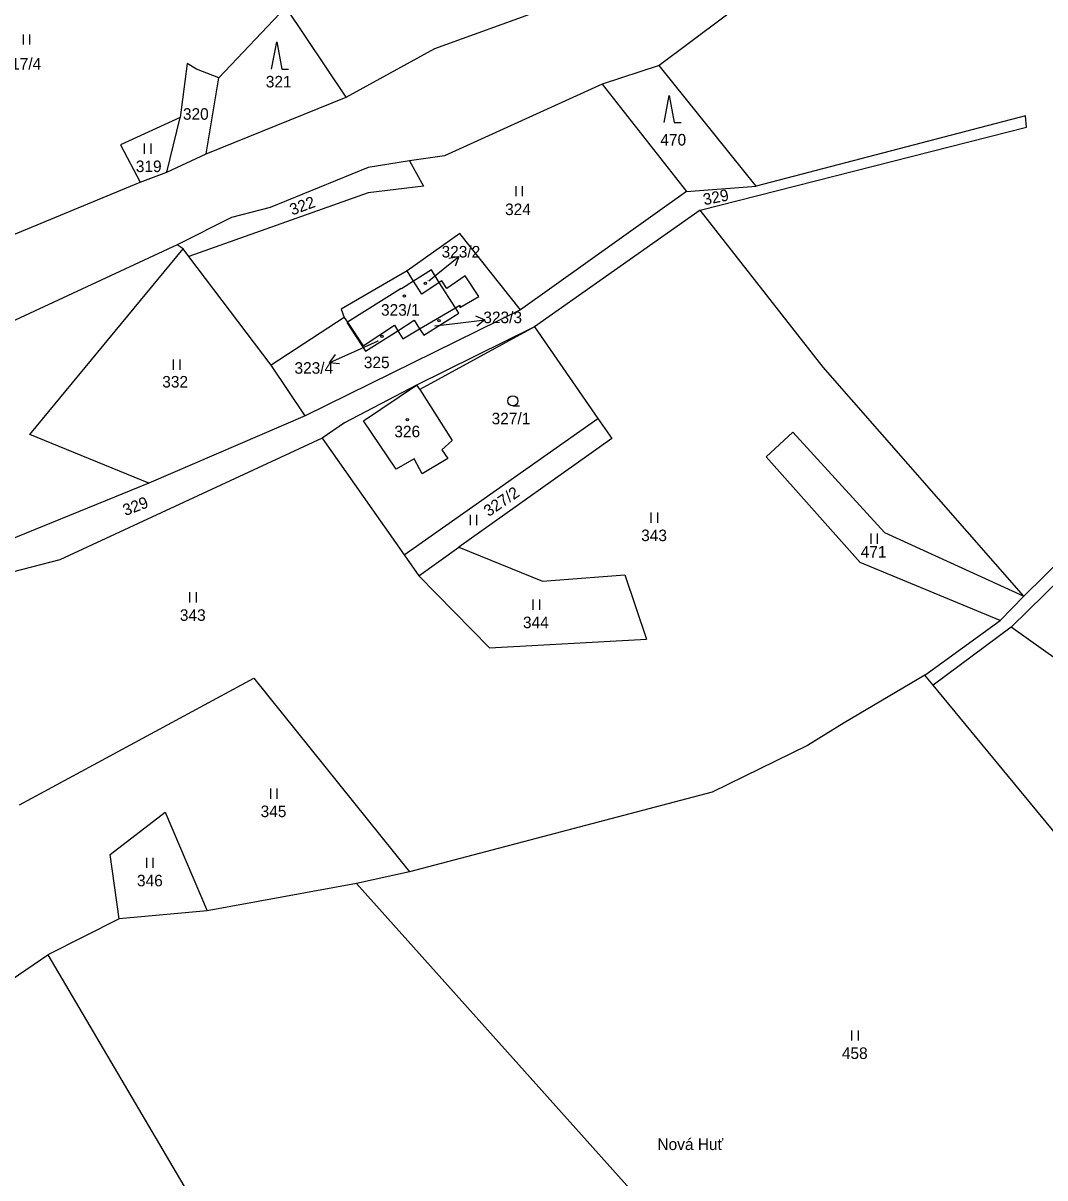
# Model space of a CAD drawing. Extents: x -670359 to -668019, y -978807 to -976674.
# Drawn here: x -669029.4 to -668879.1, y -977159.1 to -976989.2 of the extents above; entities that cross this region are included whole.
import ezdxf

# ---------------------------------------------------------------- set-up
doc = ezdxf.new("R2010")
doc.units = 0
for name, color, linetype in [('Hranice parcel', 7, 'Continuous'), ('Parcelní čísla', 7, 'Continuous'), ('Pop  PČ popisy', 7, 'Continuous'), ('Vnitřní kresba', 7, 'Continuous'), ('Značky budov', 7, 'Continuous'), ('Značky kultur', 7, 'Continuous')]:
    doc.layers.add(name, color=color, linetype=linetype)

msp = doc.modelspace()

# ---------------------------------------------------------------- linework, layer by layer
at = {"layer": 'Hranice parcel'}
for points in [[(-668916.6, -976981.01), (-668935.83, -976995.43)], [(-668990.71, -976986.86), (-669000.59, -976997.23)], [(-668981.86, -977000.08), (-668990.71, -976986.86)], [(-668968.82, -976992.93), (-668953.09, -976987.25)], [(-668981.86, -977000.08), (-668968.82, -976992.93)], [(-669005.23, -976995.14), (-669006.29, -977003.05)], [(-669003.87, -976995.94), (-669005.23, -976995.14)], [(-669001.47, -976996.91), (-669003.87, -976995.94)], [(-668935.83, -976995.43), (-668944.22, -976998.16)], [(-668921.54, -977013.15), (-668935.83, -976995.43)], [(-669002.47, -977008.43), (-669000.59, -976997.23)], [(-669000.59, -976997.23), (-669001.47, -976996.91)], [(-668944.22, -976998.16), (-668967.4, -977008.72)], [(-668944.22, -976998.16), (-668931.79, -977013.98)], [(-669002.47, -977008.43), (-668981.86, -977000.08)], [(-668881.92, -977002.82), (-668921.54, -977013.15)], [(-668881.8, -977004.5), (-668881.92, -977002.82)], [(-669006.29, -977003.05), (-669015.04, -977007.11)], [(-669008.24, -977011.13), (-669006.29, -977003.05)], [(-668929.8, -977016.71), (-668881.8, -977004.5)], [(-669015.04, -977007.11), (-669012.17, -977012.56)], [(-669008.24, -977011.13), (-669002.47, -977008.43)], [(-668972.53, -977009.47), (-668978.62, -977010.45)], [(-668967.4, -977008.72), (-668972.53, -977009.47)], [(-668972.53, -977009.47), (-668970.46, -977013.15)], [(-669012.17, -977012.56), (-669008.24, -977011.13)], [(-668978.62, -977010.45), (-668993.05, -977016.29)], [(-669052.45, -977029.26), (-669012.17, -977012.56)], [(-668978.63, -977014.17), (-669005, -977023.5)], [(-668970.46, -977013.15), (-668978.63, -977014.17)], [(-668931.79, -977013.98), (-668956.19, -977031.36)], [(-668931.79, -977013.98), (-668921.54, -977013.15)], [(-668993.05, -977016.29), (-668998.74, -977017.8)], [(-668998.74, -977017.8), (-669006.72, -977021.8)], [(-668929.8, -977016.71), (-668954.16, -977033.88)], [(-668911.7, -977039.8), (-668929.8, -977016.71)], [(-668965.12, -977020.13), (-668972.9, -977025.63)], [(-668956.19, -977031.36), (-668965.12, -977020.13)], [(-669006.72, -977021.8), (-669055.8, -977044.62)], [(-669028.39, -977049.72), (-669005.85, -977022.4)], [(-669005.85, -977022.4), (-669006.72, -977021.8)], [(-669005, -977023.5), (-669005.85, -977022.4)], [(-668992.89, -977039.49), (-669005, -977023.5)], [(-668972.9, -977025.63), (-668982.61, -977031.28)], [(-668971.95, -977027.15), (-668972.9, -977025.63)], [(-668968.16, -977027.33), (-668969.32, -977025.5), (-668971.95, -977027.15)], [(-668964.34, -977026.37), (-668967.07, -977028.21)], [(-668962.35, -977029.42), (-668964.34, -977026.37)], [(-668970.75, -977029.08), (-668971.95, -977027.15)], [(-668968.16, -977027.33), (-668970.75, -977029.08)], [(-668967.78, -977027.08), (-668968.16, -977027.33)], [(-668967.07, -977028.21), (-668967.78, -977027.08)], [(-668965.15, -977031.01), (-668962.35, -977029.42)], [(-668956.19, -977031.36), (-668987.87, -977046.95)], [(-668982.61, -977031.28), (-668982.13, -977032.48)], [(-668971.05, -977034.18), (-668970.45, -977035.12), (-668965.29, -977031.87), (-668965.79, -977031.07)], [(-668971.05, -977034.18), (-668965.79, -977031.07)], [(-668965.79, -977031.07), (-668965.15, -977030.69)], [(-668965.15, -977030.69), (-668965.15, -977031.01)], [(-668982.13, -977032.48), (-668992.89, -977039.49)], [(-668982.13, -977032.48), (-668981.66, -977033.19)], [(-668981.66, -977033.19), (-668981.74, -977033.25)], [(-668981.74, -977033.25), (-668979.02, -977037.47), (-668974.25, -977034.44)], [(-668981.66, -977033.19), (-668979.35, -977036.65)], [(-668979.35, -977036.65), (-668974.77, -977033.62)], [(-668974.77, -977033.62), (-668974.25, -977034.44)], [(-668974.25, -977034.44), (-668973.5, -977035.63)], [(-668973.5, -977035.63), (-668971.05, -977034.18)], [(-668954.16, -977033.88), (-668971.52, -977042.43)], [(-668954.16, -977033.88), (-668944.83, -977047.37)], [(-668987.87, -977046.95), (-668992.89, -977039.49)], [(-668882.19, -977073.48), (-668911.7, -977039.8)], [(-668849.2, -977041.1), (-668882.19, -977073.48)], [(-668971.52, -977042.43), (-668982.11, -977048.01)], [(-668979.3, -977047.69), (-668971.52, -977042.43)], [(-668971.52, -977042.43), (-668971.04, -977043.08)], [(-668971.04, -977043.08), (-668966.26, -977050.61)], [(-668847.36, -977042.09), (-668884.04, -977078.04)], [(-668987.87, -977046.95), (-669010.88, -977056.89)], [(-668982.11, -977048.01), (-668985.4, -977050.24)], [(-668974.52, -977054.83), (-668979.3, -977047.69)], [(-668973.34, -977067.43), (-668944.83, -977047.37)], [(-668944.83, -977047.37), (-668942.8, -977050.3)], [(-669010.88, -977056.89), (-669028.39, -977049.72)], [(-668985.4, -977050.24), (-669023.97, -977068.13)], [(-668985.4, -977050.24), (-668973.34, -977067.43)], [(-668942.8, -977050.3), (-668965.27, -977066.29)], [(-668920.07, -977052.98), (-668916.14, -977049.39)], [(-668916.14, -977049.39), (-668902.65, -977064.15)], [(-668966.26, -977050.61), (-668967.79, -977051.97)], [(-668967.79, -977051.97), (-668966.91, -977053.25)], [(-668971.87, -977053.31), (-668974.52, -977054.83)], [(-668970.68, -977055.48), (-668971.87, -977053.31)], [(-668966.91, -977053.25), (-668970.68, -977055.48)], [(-668906.27, -977068.54), (-668920.07, -977052.98)], [(-669010.88, -977056.89), (-669036.7, -977067.38)], [(-668902.65, -977064.15), (-668882.19, -977073.48)], [(-668973.34, -977067.43), (-668971.19, -977070.5)], [(-668971.19, -977070.5), (-668965.27, -977066.29)], [(-668965.27, -977066.29), (-668952.96, -977071.29)], [(-669023.97, -977068.13), (-669038.07, -977071.77)], [(-668885.64, -977077.08), (-668906.27, -977068.54)], [(-668971.19, -977070.5), (-668960.76, -977081.11)], [(-668952.96, -977071.29), (-668940.87, -977070.36)], [(-668940.87, -977070.36), (-668937.7, -977079.81)], [(-668885.64, -977077.08), (-668882.19, -977073.48)], [(-668896.72, -977085.13), (-668885.64, -977077.08)], [(-668884.04, -977078.04), (-668895.52, -977086.57)], [(-668843.95, -977106.55), (-668884.04, -977078.04)], [(-668960.76, -977081.11), (-668937.7, -977079.81)], [(-669029.93, -977104.2), (-668995.44, -977085.57)], [(-668995.44, -977085.57), (-668972.56, -977114.04)], [(-668896.72, -977085.13), (-668908.59, -977092.13)], [(-668895.52, -977086.57), (-668896.72, -977085.13)], [(-668863.63, -977125.22), (-668895.52, -977086.57)], [(-668908.59, -977092.13), (-668913.97, -977095.48)], [(-668913.97, -977095.48), (-668928, -977102.32)], [(-668928, -977102.32), (-668972.56, -977114.04)], [(-669016.59, -977111.52), (-669008.48, -977105.3)], [(-669008.48, -977105.3), (-669002.28, -977119.8)], [(-669015.26, -977120.96), (-669016.59, -977111.52)], [(-668972.56, -977114.04), (-668980.33, -977115.78)], [(-668980.33, -977115.78), (-669002.28, -977119.8)], [(-668932.58, -977169.12), (-668980.33, -977115.78)], [(-669002.28, -977119.8), (-669015.26, -977120.96)], [(-669015.26, -977120.96), (-669025.76, -977126.29)], [(-669031.15, -977129.95), (-669025.76, -977126.29)], [(-669025.76, -977126.29), (-668965.38, -977228.83)]]:
    msp.add_lwpolyline(points, dxfattribs=at)
at = {"layer": 'Parcelní čísla'}
for p, q in [((-668966.74, -977023.75), (-668965.26, -977023.52)), ((-668969.71, -977027.08), (-668968.38, -977026.02)), ((-668968.81, -977033.7), (-668965.42, -977033.31)), ((-668962.82, -977032.26), (-668961.45, -977032.85)), ((-668977.22, -977035.98), (-668980.68, -977037.53)), ((-668982.84, -977039.32), (-668984.33, -977039.16))]:
    msp.add_line(p, q, dxfattribs=at)
for points in [[(-668968.38, -977026.02), (-668965.26, -977023.52), (-668965.8, -977024.92)], [(-668965.42, -977033.31), (-668961.45, -977032.85), (-668962.65, -977033.75)], [(-668980.68, -977037.53), (-668984.33, -977039.16), (-668983.45, -977037.95)]]:
    msp.add_lwpolyline(points, dxfattribs=at)
at = {"layer": 'Vnitřní kresba'}
for p, q in [((-668973.77, -977028.21), (-668981.66, -977033.19)), ((-668973.72, -977028.29), (-668973.77, -977028.21)), ((-668971.95, -977027.15), (-668973.72, -977028.29)), ((-668965.79, -977031.07), (-668968.16, -977027.33)), ((-668974.25, -977034.44), (-668971.86, -977032.91)), ((-668971.86, -977032.91), (-668971.05, -977034.18))]:
    msp.add_line(p, q, dxfattribs=at)
msp.add_lwpolyline([(-668954.16, -977033.88), (-668971.04, -977043.08)], dxfattribs=at)
at = {"layer": 'Značky budov'}
for centre in [(-668973.3, -977029.35), (-668972.88, -977047.52)]:
    msp.add_circle(centre, 0.175, dxfattribs=at)
at = {"layer": 'Značky kultur'}
for p, q in [((-669029.37, -976990.84), (-669029.37, -976992.34)), ((-669028.37, -976992.34), (-669028.37, -976990.84)), ((-669011.55, -977006.9), (-669011.55, -977008.4)), ((-669010.55, -977008.4), (-669010.55, -977006.9)), ((-668956.92, -977013.15), (-668956.92, -977014.65)), ((-668955.92, -977014.65), (-668955.92, -977013.15)), ((-669007.3, -977038.69), (-669007.3, -977040.19)), ((-669006.3, -977040.19), (-669006.3, -977038.69)), ((-668957.35, -977045.51), (-668956.35, -977045.51)), ((-668963.64, -977061.53), (-668963.64, -977063.03)), ((-668962.64, -977063.03), (-668962.64, -977061.53)), ((-668937.03, -977061.2), (-668937.03, -977062.7)), ((-668936.03, -977062.7), (-668936.03, -977061.2)), ((-668904.68, -977064.29), (-668904.68, -977065.79)), ((-668903.68, -977065.79), (-668903.68, -977064.29)), ((-669004.89, -977072.93), (-669004.89, -977074.43)), ((-669003.89, -977074.43), (-669003.89, -977072.93)), ((-668954.39, -977074.01), (-668954.39, -977075.51)), ((-668953.39, -977075.51), (-668953.39, -977074.01)), ((-668993.01, -977101.81), (-668993.01, -977103.31)), ((-668992.01, -977103.31), (-668992.01, -977101.81)), ((-669011.24, -977111.99), (-669011.24, -977113.49)), ((-669010.24, -977113.49), (-669010.24, -977111.99)), ((-668907.51, -977137.39), (-668907.51, -977138.89)), ((-668906.51, -977138.89), (-668906.51, -977137.39))]:
    msp.add_line(p, q, dxfattribs=at)
for points in [[(-668992.82, -976995.95), (-668992.07, -976991.95), (-668991.32, -976995.95), (-668990.32, -976995.95)], [(-668935.09, -977003.81), (-668934.34, -976999.81), (-668933.59, -977003.81), (-668932.59, -977003.81)]]:
    msp.add_lwpolyline(points, dxfattribs=at)
for centre, radius in [((-668970.21, -977027.47), 0.175), ((-668973.3, -977029.35), 0.175), ((-668968.2, -977032.95), 0.175), ((-668976.57, -977035.27), 0.175), ((-668957.35, -977044.76), 0.75), ((-668972.88, -977047.52), 0.175)]:
    msp.add_circle(centre, radius, dxfattribs=at)

# ---------------------------------------------------------------- texts
at = {"layer": 'Parcelní čísla'}
for s, height, p in [('317/4', 1.7, (-669032.41, -976996.03)), ('321', 1.7, (-668993.68, -976998.65)), ('320', 1.7, (-669005.87, -977003.4)), ('470', 1.7, (-668935.64, -977007.19)), ('319', 1.7, (-669012.8, -977011.1)), ('324', 1.7, (-668958.48, -977017.43)), ('323/2', 1.7, (-668967.82, -977023.67)), ('323/2', 0.1, (-668969.91, -977027.08)), ('323/1', 1.7, (-668976.73, -977032.23)), ('323/3', 1.7, (-668961.68, -977033.33)), ('323/3', 0.1, (-668969.01, -977033.7)), ('323/4', 0.1, (-668977.42, -977035.98)), ('325', 1.7, (-668979.26, -977039.95)), ('323/4', 1.7, (-668989.46, -977040.77)), ('332', 1.7, (-669008.91, -977042.8)), ('327/1', 1.7, (-668960.46, -977048.21)), ('326', 1.7, (-668974.77, -977050.12)), ('343', 1.7, (-668938.46, -977065.4)), ('471', 1.7, (-668906.16, -977067.81)), ('343', 1.7, (-669006.32, -977077.13)), ('344', 1.7, (-668955.85, -977078.21)), ('345', 1.7, (-668994.44, -977106.01)), ('346', 1.7, (-669012.63, -977116.19)), ('458', 1.7, (-668908.94, -977141.59))]:
    msp.add_text(s, height=height, dxfattribs=at).set_placement(p)
for s, rotation, p in [('322', 20.3495, (-668989.8, -977017.5)), ('329', 11.3099, (-668929.17, -977015.99)), ('329', 20.879, (-669014.34, -977061.72)), ('327/2', 34.2563, (-668960.9, -977061.87))]:
    msp.add_text(s, height=1.7, rotation=rotation, dxfattribs=at).set_placement(p)
at = {"layer": 'Pop  PČ popisy'}
msp.add_text('Nová Huť', height=1.7, dxfattribs=at).set_placement((-668936.07, -977154.99))

doc.saveas('drawing.dxf')
